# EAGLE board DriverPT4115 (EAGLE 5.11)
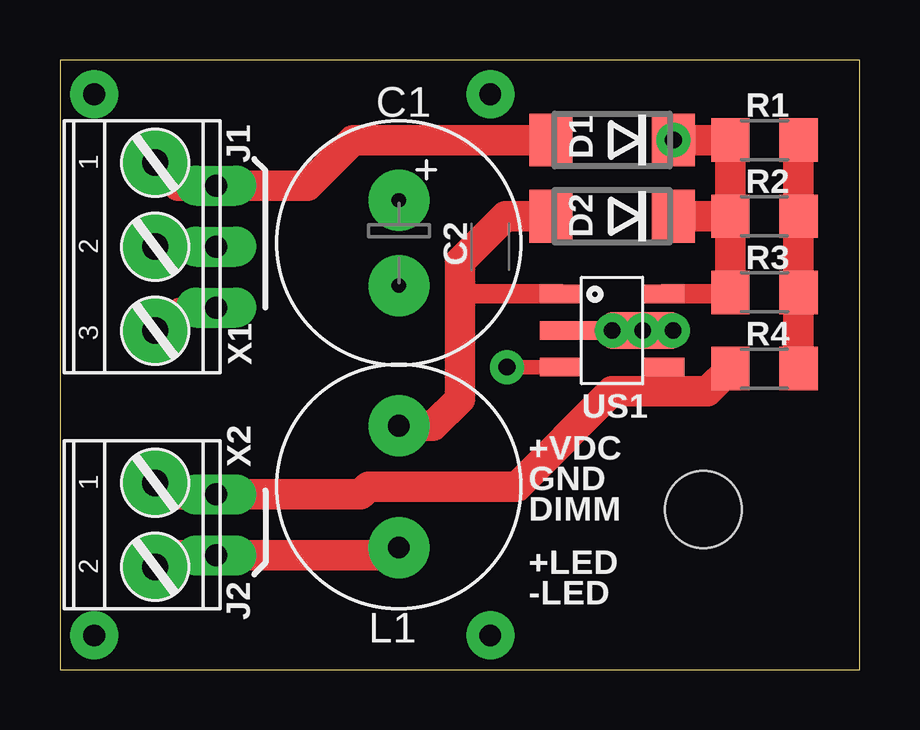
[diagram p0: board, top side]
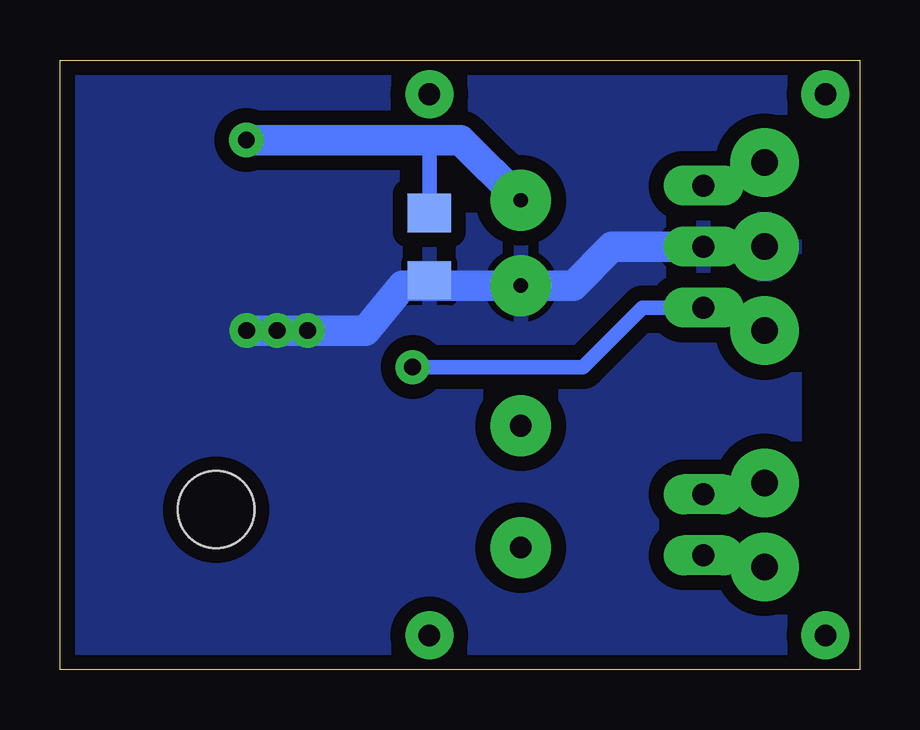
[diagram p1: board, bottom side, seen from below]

Size 33.34 x 25.4 mm. Coordinates in mm from the lower left corner, seen from the top.
Outline: 0,0 33.34,0 33.34,25.4 0,25.4 0,0
Copper layers (1*16): Top 0.035mm / dielectric 1.5mm / Bottom 0.035mm
Design rules "default *": minimum track width 10mil, minimum drill 24mil, track to track 8mil, track to pad 8mil, pad to pad 8mil, via to via 8mil, smd to smd 8mil, copper to edge 15mil, drill to drill 8mil, minimum pad ring 10mil, minimum via ring 8mil, stop-mask expansion 4mil, vias tented up to drill 32mil, thermal gap 10mil
Holes 3.2 mm at 26.83,6.67

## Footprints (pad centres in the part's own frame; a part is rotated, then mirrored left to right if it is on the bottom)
E3,5-10 = drill 0.6 pad 2.54 round: + -1.778,0; - 1.778,0
C1206_TOP/BOT = smd 1.6 x 1.8 bottom: 1 -1.4,0; 2 1.4,0
DO214AA = smd 1.8 x 2.2: A 2.55,0; C -2.55,0
7395-03_TRANSPARENT = drill 0.914 pad 1.676 long: 1 2.54,0; 2 0,0; 3 -2.54,0
7395-02_TRANSPARENT = drill 0.914 pad 1.676 long: 1 1.27,0; 2 -1.27,0
9X12 = drill 0.9 pad 2.54 round: 1 0,2.54; 2 0,-2.54
R1206 = smd 1.6 x 1.803: 1 -1.422,0; 2 1.422,0
SOT89-5 = smd 0.762 x 1.778: 1 -1.524,-2.127; 3 1.524,-2.127; 4 1.524,2.127; 5 -1.524,2.127 | smd 0.762 x 2.54: 2 0,-1.746 | smd 1.524 x 3.556: EXPOSED_PAD 0,1.238
AK550/3 = drill 1.1 pad 2.857 round: 1 -3.5,0; 2 0,0; 3 3.5,0
AK550/2 = drill 1.1 pad 2.857 round: 1 -1.75,0; 2 1.75,0

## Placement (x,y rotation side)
C1  470uF  [E3,5-10]  14.13,17.78 270 top
C2  100nF  [C1206_TOP/BOT]  17.94,17.62 270 top
D1  SS14  [DO214AA]  23.02,22.07 180 top
D2  SS14  [DO214AA]  23.02,18.89 180 top
J1  [7395-03_TRANSPARENT]  6.51,17.62 270 top
J2  [7395-02_TRANSPARENT]  6.51,6.03 270 top
L1  *  [9X12]  14.13,7.62 0 top
R1  *  [R1206]  29.37,18.89 0 top
R2  *  [R1206]  29.37,22.07 180 top
R3  *  [R1206]  29.37,15.72 180 top
R4  *  [R1206]  29.37,12.54 0 top
US1  PT4115  [SOT89-5]  23.02,14.13 270 top
X1  [AK550/3]  3.97,17.62 270 top
X2  [AK550/2]  3.97,6.03 270 top

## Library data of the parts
C1 C2 R1-R4 = rcl
D1 D2 = diode
J1 J2 = con-molex
L1 = inductors
US1 = PT4115
X1 X2 = con-ptr500+

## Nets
GND: C1.- C2.2 J1.2 US1.2 US1.EXPOSED_PAD X1.2
N$1: J1.1 US1.3 X1.3
N$4: R1.2 R2.1 R3.1 R4.2
N$5: C1.+ C2.1 D1.C D2.C R1.1 R2.2 R3.2 US1.5
N$6: D1.A J1.3 X1.1
N$7: J2.2 R4.1 US1.4 X2.1
N$8: D2.A L1.1 US1.1
N$9: J2.1 L1.2 X2.2

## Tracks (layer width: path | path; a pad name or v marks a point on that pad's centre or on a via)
GND  (via drill 0.7 pad 1.42)
  Top 0.61: US1.2 v23.02,14.13 US1.EXPOSED_PAD
  Top 0.813: v25.56,14.13 v24.29,14.13 v23.02,14.13
  Bottom 0.61: 17.94,16 C2.2
  Bottom 1.27: X1.2 J1.2 10.32,17.62 11.94,16 C1.- 17.94,16 19.05,16 20.61,14.13 v23.02,14.13 v24.29,14.13 v25.56,14.13
  pour Bottom (isolate 0.61): 33.18,25.24 2.7,25.24 2.7,0.16 33.18,0.16
N$1  (via drill 0.7 pad 1.42)
  Top 0.61: v18.64,12.6 US1.3
  Top 0.813: X1.3 4.93,15.08 J1.1
  Bottom 0.61: J1.1 9.05,15.08 11.53,12.6 v18.64,12.6
N$2  (via drill 0.9 pad 2)
  other vias: 17.94,1.43
N$4
  Top 1.27: R2.1 R1.2 R3.1 R4.2
N$5  (via drill 0.7 pad 1.42)
  Top 0.813: US1.5 27.69,15.65 R3.2
  Top 1.27: R2.2 R1.1 | R1.1 R3.2 | R2.2 27.95,21.58 | D1.C R2.2 | R1.1 D2.C
  Bottom 0.61: 17.94,22.07 C2.1
  Bottom 1.27: D1.C 17.94,22.07 16.64,22.07 C1.+
  other vias: 25.57,22.07
N$6
  Top 1.27: X1.1 4.93,20.16 J1.3 10.32,20.16 12.22,22.07 D1.A
N$7
  Top 0.61: US1.4 25.15,12 24.29,11.59
  Top 1.27: R4.1 26.99,11.59 24.29,11.59 23.02,11.59 19.05,7.62 12.86,7.62 12.54,7.3 J2.2 4.45,7.3 X2.1
N$8
  Top 0.813: 16.67,15.65 US1.1
  Top 1.27: L1.1 15.56,10.16 16.67,11.27 16.67,15.65 16.67,16.99 18.57,18.89 D2.A
N$9
  Top 1.27: L1.2 13.81,4.76 J2.1 4.45,4.76 X2.2
N$10  (via drill 0.9 pad 2)
  other vias: 17.94,23.97
N$11  (via drill 0.9 pad 2)
  other vias: 1.43,23.97
N$12  (via drill 0.9 pad 2)
  other vias: 1.43,1.43

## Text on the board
tNames: +VDC | GND | DIMM | +LED | -LED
